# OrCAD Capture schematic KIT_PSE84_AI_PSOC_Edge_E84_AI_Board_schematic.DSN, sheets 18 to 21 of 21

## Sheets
18 21. Revision History
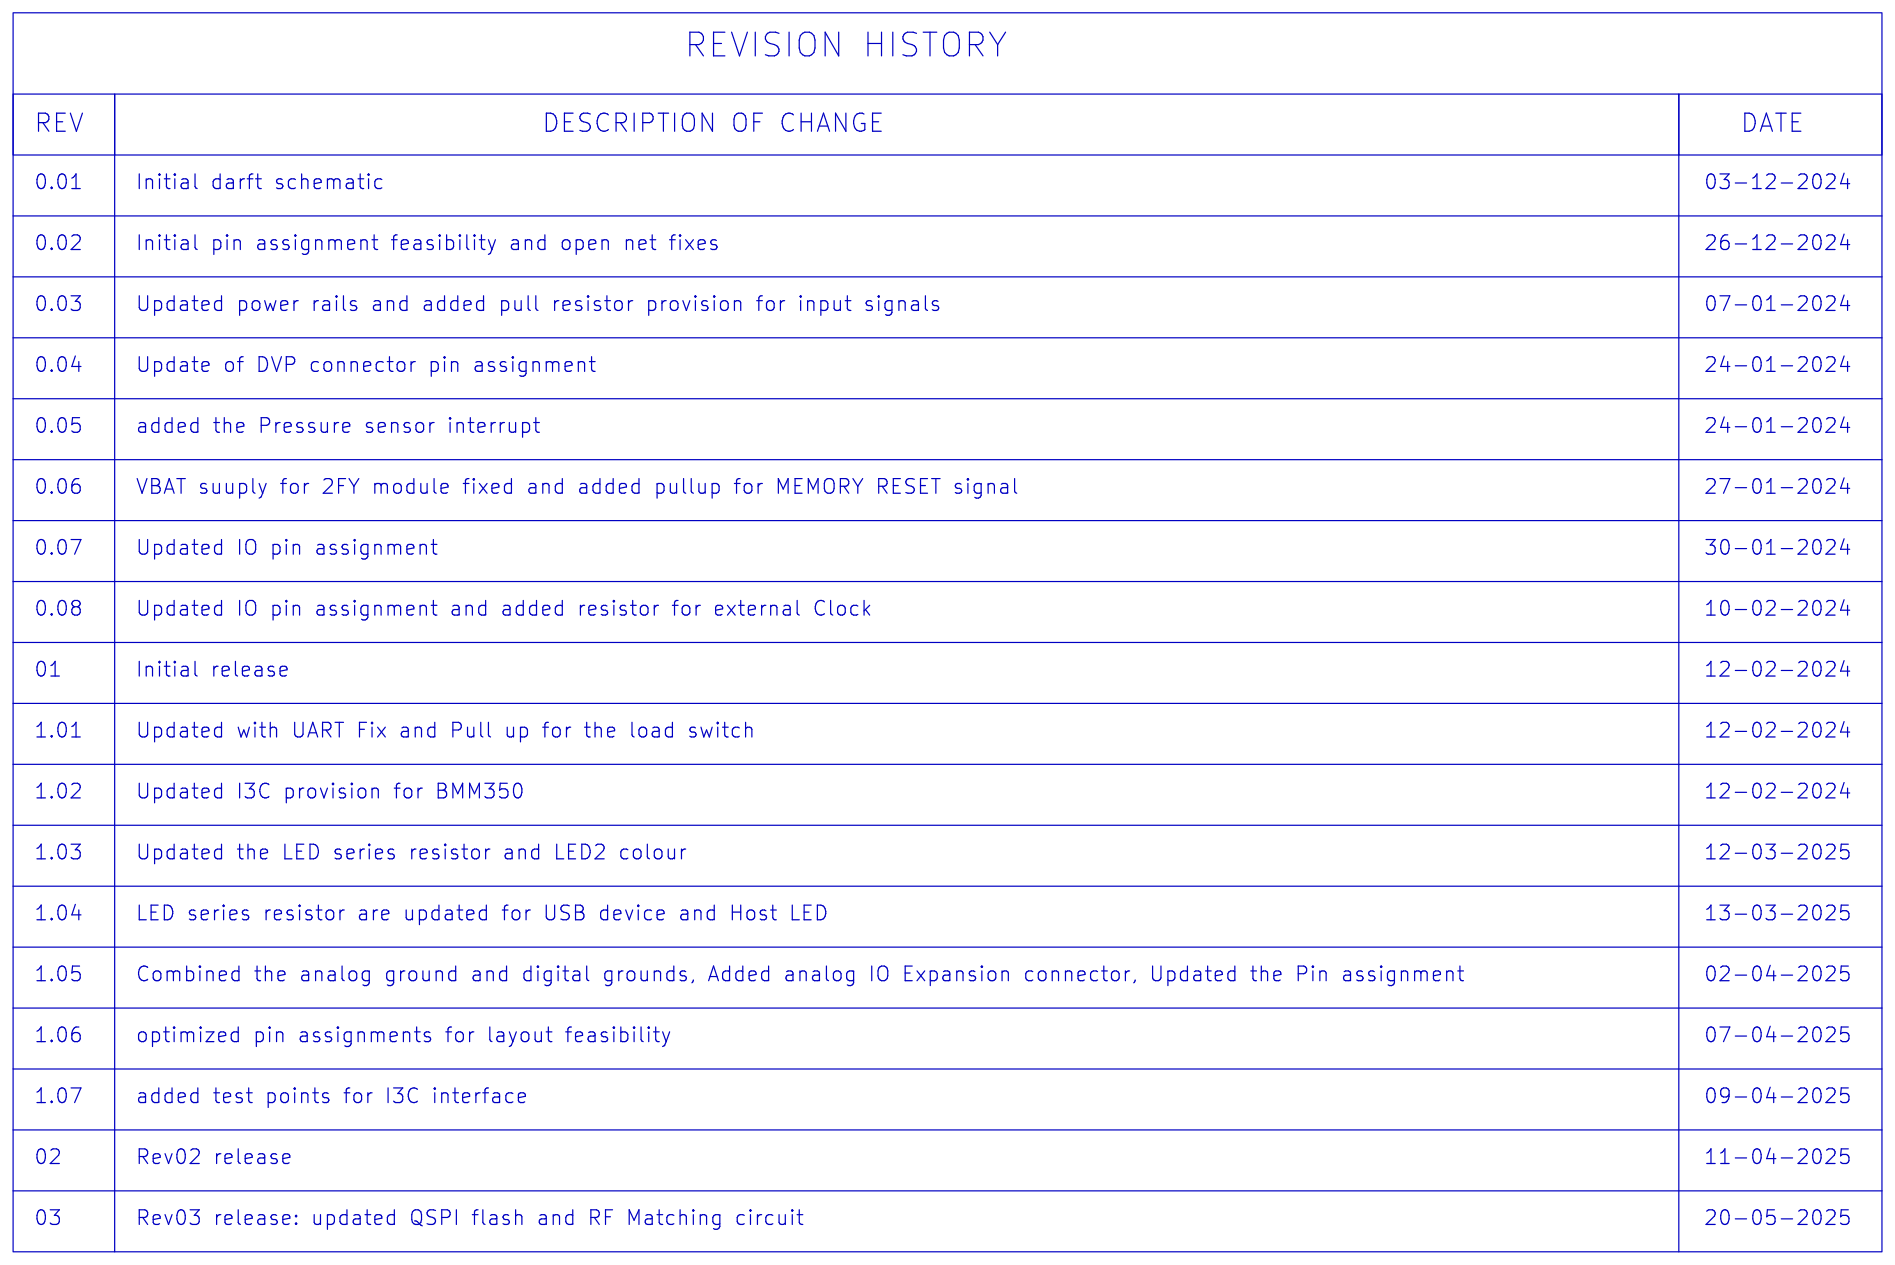
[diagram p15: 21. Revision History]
19 19. PSOC™ E84 Signals: size A4
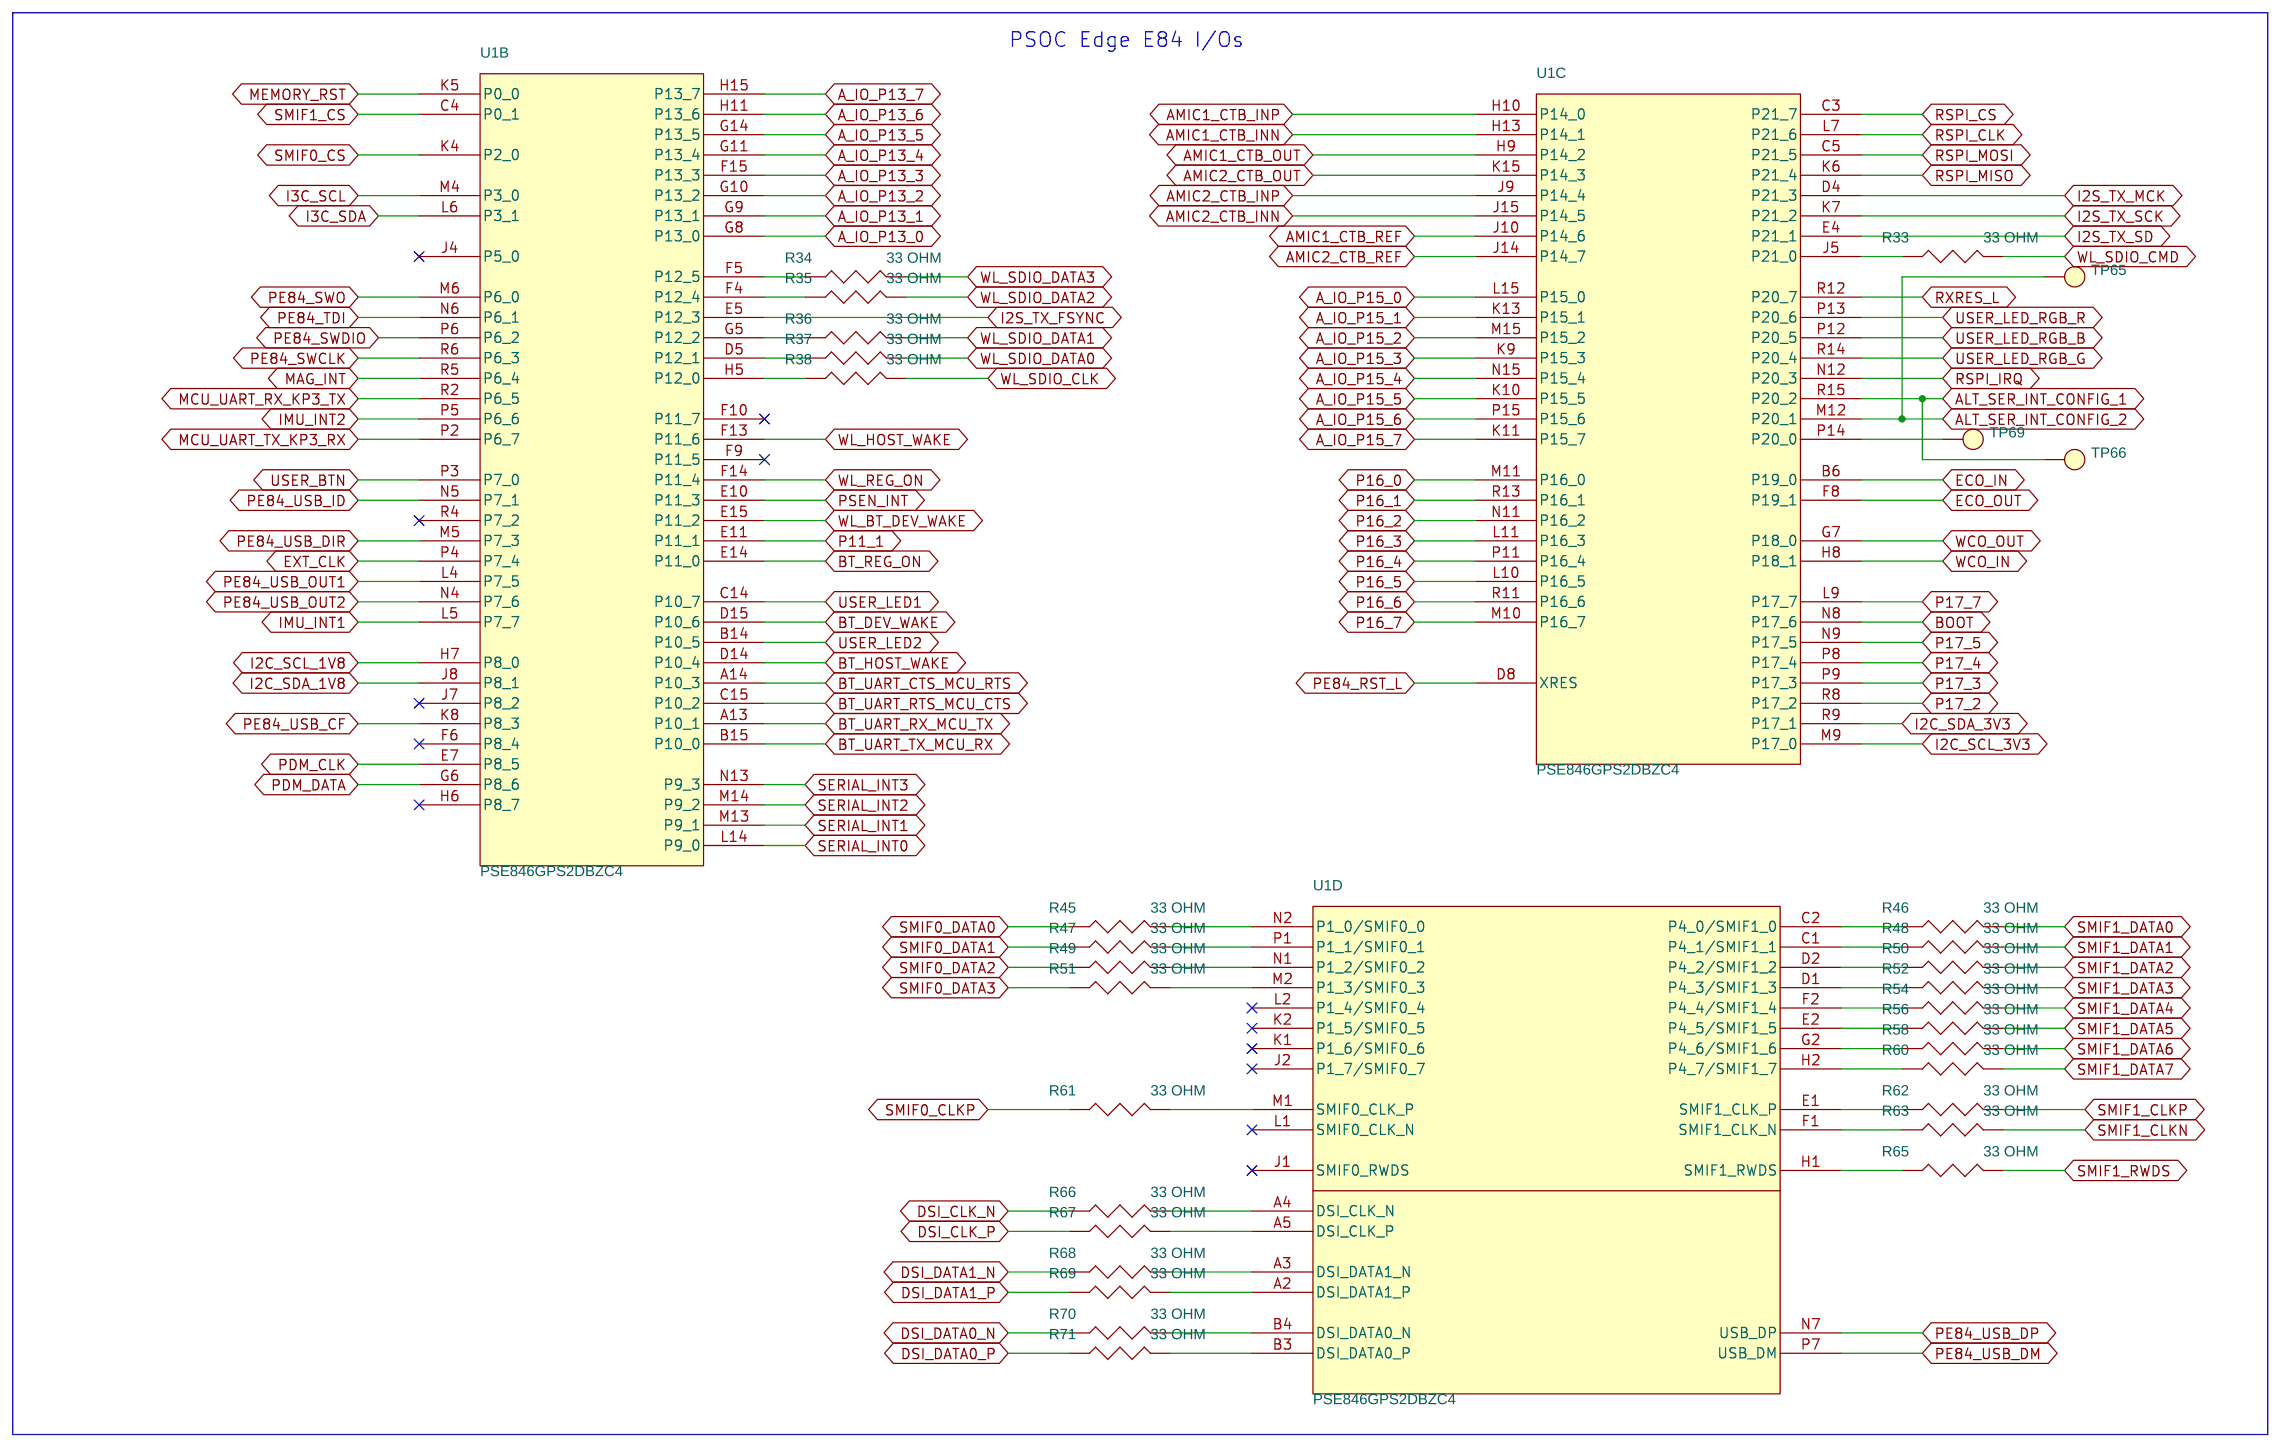
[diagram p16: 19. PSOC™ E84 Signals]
20 18. PSOC™ Edge E84 Power2: size A4
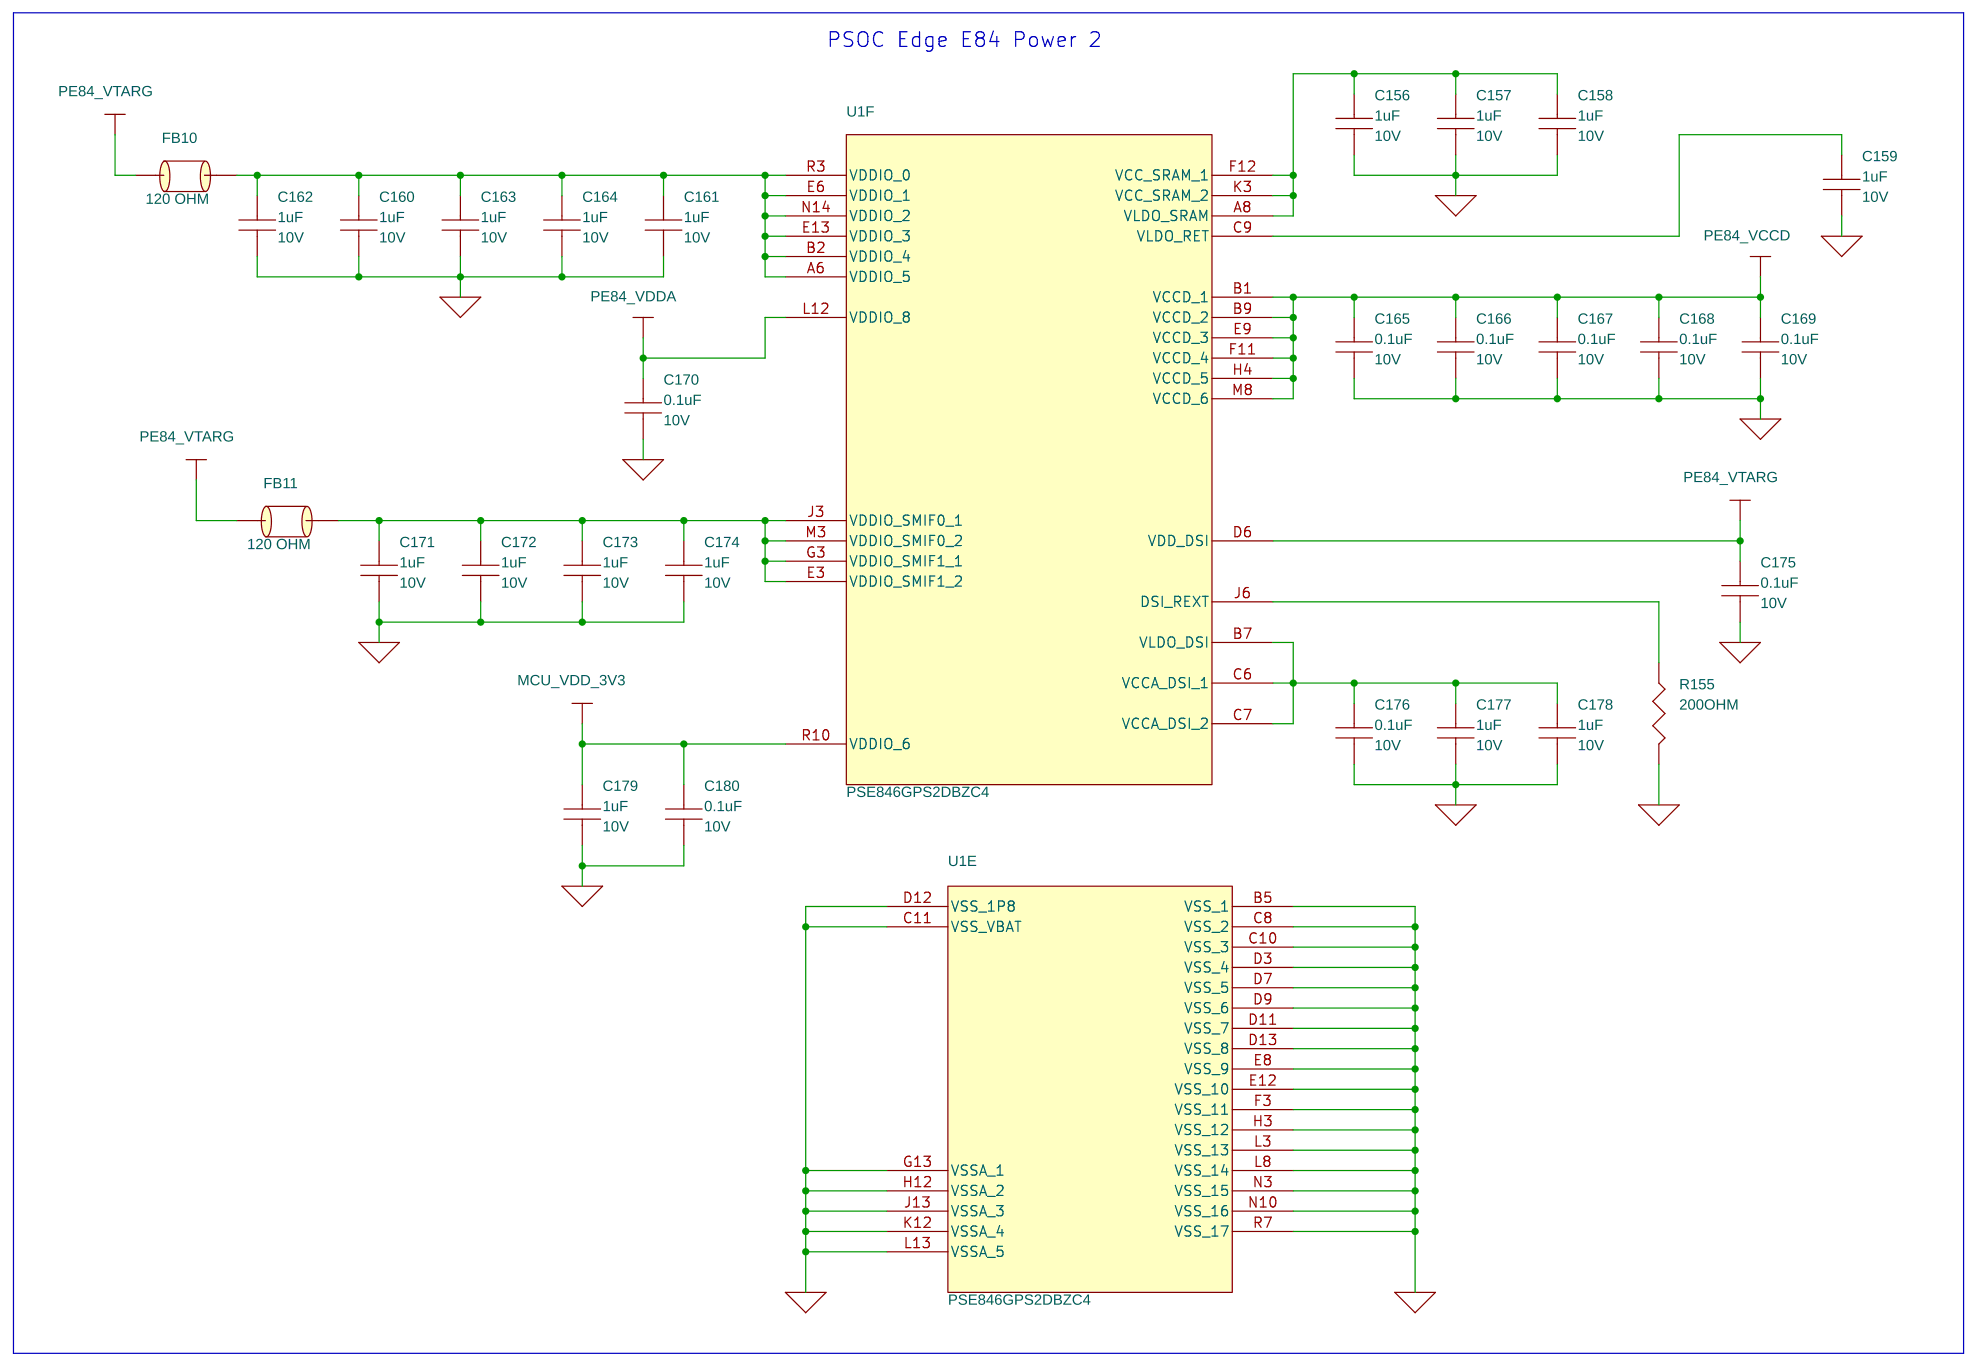
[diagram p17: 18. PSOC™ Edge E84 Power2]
21 17. PSOC™ Edge E84 Power1: size A4
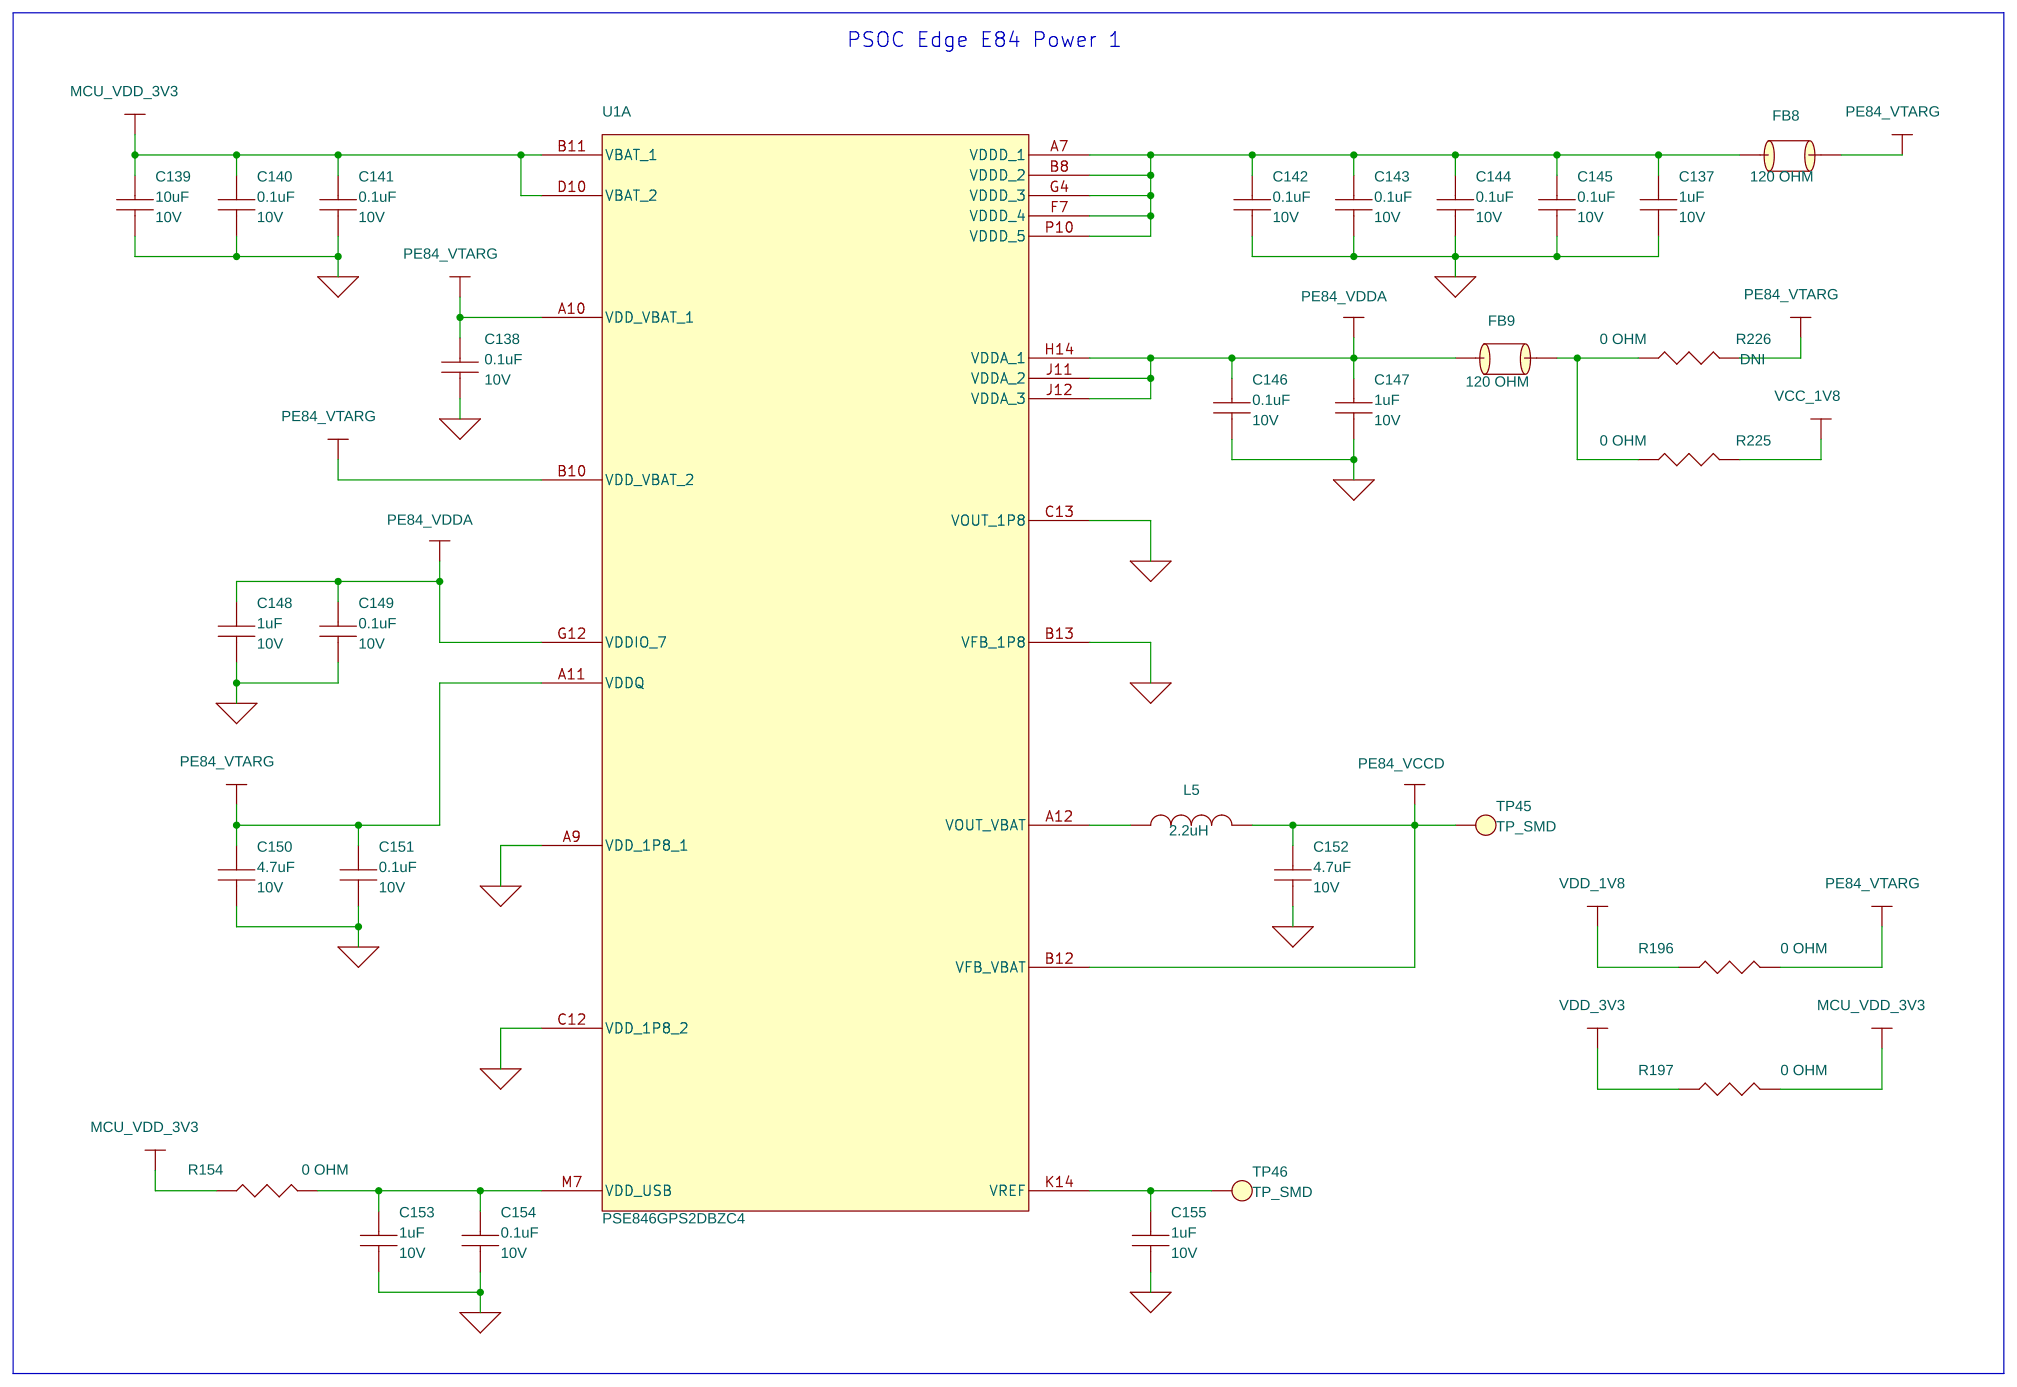
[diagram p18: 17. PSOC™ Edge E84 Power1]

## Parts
sheet 17. PSOC™ Edge E84 Power1
C137  1uF  [CAPC0603_0201N]
C138  0.1uF  [CAPC0603_0201N]
C139  10uF  [CAPC1005_0402N]
C140  0.1uF  [CAPC0603_0201N]
C141  0.1uF  [CAPC0603_0201N]
C142  0.1uF  [CAPC0603_0201N]
C143  0.1uF  [CAPC0603_0201N]
C144  0.1uF  [CAPC0603_0201N]
C145  0.1uF  [CAPC0603_0201N]
C146  0.1uF  [CAPC0603_0201N]
C147  1uF  [CAPC0603_0201N]
C148  1uF  [CAPC0603_0201N]
C149  0.1uF  [CAPC0603_0201N]
C150  4.7uF  [CAPC1005_0402N]
C151  0.1uF  [CAPC0603_0201N]
C152  4.7uF  [CAPC1005_0402N]
C153  1uF  [CAPC0603_0201N]
C154  0.1uF  [CAPC0603_0201N]
C155  1uF  [CAPC0603_0201N]
FB8  120 OHM  [INDC1005_0402M]
FB9  120 OHM  [INDC1005_0402M]
L5  2.2uH  [IND_74479276222C]
R154  0 OHM  [RESC1005_0402N]
R196  0 OHM  [RESC1005_0402N]
R197  0 OHM  [RESC1005_0402N]
R225  0 OHM  [RESC1005_0402N]
R226  0 OHM  [RESC1005_0402N]
TP45  TP_SMD  [ict_tp_smd_030rd_nsp]
TP46  TP_SMD  [ict_tp_smd_030rd_nsp]
sheet 18. PSOC™ Edge E84 Power2
C156  1uF  [CAPC0603_0201N]
C157  1uF  [CAPC0603_0201N]
C158  1uF  [CAPC0603_0201N]
C159  1uF  [CAPC0603_0201N]
C160  1uF  [CAPC0603_0201N]
C161  1uF  [CAPC0603_0201N]
C162  1uF  [CAPC0603_0201N]
C163  1uF  [CAPC0603_0201N]
C164  1uF  [CAPC0603_0201N]
C165  0.1uF  [CAPC0603_0201N]
C166  0.1uF  [CAPC0603_0201N]
C167  0.1uF  [CAPC0603_0201N]
C168  0.1uF  [CAPC0603_0201N]
C169  0.1uF  [CAPC0603_0201N]
C170  0.1uF  [CAPC0603_0201N]
C171  1uF  [CAPC0603_0201N]
C172  1uF  [CAPC0603_0201N]
C173  1uF  [CAPC0603_0201N]
C174  1uF  [CAPC0603_0201N]
C175  0.1uF  [CAPC0603_0201N]
C176  0.1uF  [CAPC0603_0201N]
C177  1uF  [CAPC0603_0201N]
C178  1uF  [CAPC0603_0201N]
C179  1uF  [CAPC0603_0201N]
C180  0.1uF  [CAPC0603_0201N]
FB10  120 OHM  [INDC1005_0402M]
FB11  120 OHM  [INDC1005_0402M]
R155  200OHM  [RESC0603_0201N]
U1  PSE846GPS2DBZC4  [BGA220C65P15X15_1000X1000X100_EXPLORER]  (sections A,B,C,D,E,F)
sheet 19. PSOC™ E84 Signals
R33  33 OHM  [RESC0603_0201N]
R34  33 OHM  [RESC0603_0201N]
R35  33 OHM  [RESC0603_0201N]
R36  33 OHM  [RESC0603_0201N]
R37  33 OHM  [RESC0603_0201N]
R38  33 OHM  [RESC0603_0201N]
R45  33 OHM  [RESC0603_0201N]
R46  33 OHM  [RESC0603_0201N]
R47  33 OHM  [RESC0603_0201N]
R48  33 OHM  [RESC0603_0201N]
R49  33 OHM  [RESC0603_0201N]
R50  33 OHM  [RESC0603_0201N]
R51  33 OHM  [RESC0603_0201N]
R52  33 OHM  [RESC0603_0201N]
R54  33 OHM  [RESC0603_0201N]
R56  33 OHM  [RESC0603_0201N]
R58  33 OHM  [RESC0603_0201N]
R60  33 OHM  [RESC0603_0201N]
R61  33 OHM  [RESC0603_0201N]
R62  33 OHM  [RESC0603_0201N]
R63  33 OHM  [RESC0603_0201N]
R65  33 OHM  [RESC0603_0201N]
R66  33 OHM  [RESC0603_0201N]
R67  33 OHM  [RESC0603_0201N]
R68  33 OHM  [RESC0603_0201N]
R69  33 OHM  [RESC0603_0201N]
R70  33 OHM  [RESC0603_0201N]
R71  33 OHM  [RESC0603_0201N]
TP65  TP_SMD  [ict_tp_smd_030rd_nsp]
TP66  TP_SMD  [ict_tp_smd_030rd_nsp]
TP69  TP_SMD  [ict_tp_smd_030rd_nsp]

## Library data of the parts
C137 C147 C148 C153 C155-C164 C171-C174 C177-C179 = CAP-NP: CAP, CER, 1uF, 20%, 10V, X5R, 0201; Approved: Approved; CY_PN: 510-61183-01; Device File: 510-60276-01; Device_File: 510-61183-01; Dielectric: X5R; FPLIST: CAPC0603_0201N,CAPC0603_0201Q; Lifecycle: Active; Manufacturer: Murata; Manufacturer_PN: GRM033R61A105ME15D; Operating_Temp: -55°C ~ 85°C; Package: 0201; Part Status: In Prod; Part_Status: In prod; Tolerance: 20%; Voltage: 10V
C138 C140-C146 C149 C151 C154 C165-C170 C175 C176 C180 = CAP-NP: CAP, CER, 0.1uF, 10%, X5R, 10V, 0201; Approved: Approved; CY_PN: 510-60777-01; Device_File: 510-60777-01; Dielectric: X5R; FPLIST: CAPC0603_0201N,CAPC0603_0201Q; Lifecycle: Active; Manufacturer: Wurth; Manufacturer_PN: 885012104002; Operating_Temp: -55°C ~ 85°C; Package: 0201; Part_Status: In Prod; Tolerance: 0.1; Voltage: 10V
C139 = CAP-NP: CAP, CER, 10uF, 20%, X5R, 10V, 0402; Approved: Approved; CY_PN: 510-60337-01; Device_File: 510-60337-01; Dielectric: X5R; FPLIST: CAPC1005_0402N,CAPC1005_0402M; Lifecycle: Active; Manufacturer: Wurth; Manufacturer_PN: 885012105022; Operating_Temp: -55°C ~ 85°C; Package: 0402; Part_Status: Unrel; Tolerance: 20%; Voltage: 10V
C150 C152 = CAP-NP: CAP, CER, 4.7uF, 20%, X5R, 10V, 0402; Approved: Approved; CY_PN: 510-60422-01; Device_File: 510-60422-01; Dielectric: X5R; FPLIST: CAPC1005_0402N,CAPC1005_0402M,capc1005_is0402q; Lifecycle: Active; Manufacturer: Murata; Manufacturer_PN: GRM155R61A475MEAAD; Operating_Temp: -55°C ~ 85°C; Package: 0402; Part_Status: In Prod; Tolerance: 20%; Voltage: 10V
FB8-FB11 = FB: IND, FERRITE BEAD, 120 OHM, 0402, 1LN; Approved: Approved; CY_PN: 520-60217-01; Current: 2A; DB_Status: Verified; Device_File: 520-60217-01; ESR: 55mOHM; FPLIST: INDC1005_0402M,INDC1005_0402N,INDC1005_0402L; Lifecycle: Active; Manufacturer: Murata; Manufacturer_PN: BLM15PX121SN1D; Material: Ferrite; Operating_Temp: -55°C ~ 125°C; Package: SMD; Part_Status: Unrel; Part_Type: Ferrite Bead; Tolerance: 25%
L5 = IND: IND, FIXED, SHIELDED, 2.2uH, 20%, 2.6A, 135MOHM, 0806, SMD; Approved: Approved; CY_PN: 520-60354-01; Current: 2.6A; DB_Status: Verified; Device_File: 520-60354-01; ESR: 135mOHM; Lifecycle: Active; Manufacturer: Würth Elektronik; Manufacturer_PN: 74479276222C; Material: shielded; Operating_Temp: -40°C ~ 125°C; Package: 0806; Part_Status: Unrel; Part_Type: Inductor; Tolerance: ±20%
R154 R225 = RES: RES, FIXED, 0 OHM, JUMPER, 1A, 1/16W, 0402; Approved: Approved; CY_PN: 500-60344-01; Device_File: 500-60344-01; FPLIST: RESC1005_0402N,RESC1005_0402M; Lifecycle: Active; Manufacturer: Wurth; Manufacturer_PN: 560112110001; Operating_Temp: -55°C ~ 155°C; Package: 0402; Part_Status: In Prod; Rating: 1/16W; Tolerance: JUMPER
R196 R197 = RES: RES, FIXED, 0 OHM, JUMPER, 1A, 1/16W, 0402; Approved: Approved; CY_PN: 500-60344-01; Device File: 500-60037-01; Device_File: 500-60344-01; FPLIST: RESC1005_0402N,RESC1005_0402M; Lifecycle: Active; Manufacturer: Wurth; Manufacturer_PN: 560112110001; Operating_Temp: -55°C ~ 155°C; Package: 0402; Part_Status: In Prod; Rating: 1/16W; Tolerance: JUMPER
R226 = RES: RES, FIXED, 0 OHM, JUMPER, 1A, 1/16W, 0402; Approved: Approved; CY_PN: 500-60344-01; DNI: DNI; Device_File: 500-60344-01; FPLIST: RESC1005_0402N,RESC1005_0402M; Lifecycle: Active; Manufacturer: Wurth; Manufacturer_PN: 560112110001; Operating_Temp: -55°C ~ 155°C; Package: 0402; Part_Status: In Prod; Rating: 1/16W; Tolerance: JUMPER
TP45 TP46 TP65 TP66 TP69 = TP_SMD: TestPoint, PCB, Circle, 0.75mm, SMD; Approved: Approved; CY_PN: NA; DNI: DNI; Device_File: NA; Lifecycle: NA; Manufacturer: NA; Manufacturer_PN: NA; Part_Status: NA
R155 = RES: RES 200 OHM 1% 1/20W 0201; Approved: Approved; CY_PN: 500-61242-01; Device_File: 500-61242-01; FPLIST: RESC0603_0201N,RESC0603_0201Q; Manufacturer: Stackpole; Manufacturer_PN: RMCF0201FT200R; Package: 0201; Rating: 1/20W
U1 = Explorer_220BGA_rev9280_May22: IC, Infineon, MCU, PSoC E84, Dual Core, 50/400MHz, 1.8 V / 2.7 to 4.8 V, BGA-220; Approved: Approved; Description1: 6.5MB SRAM/0.5MB RRAM, PSA L2 Security, 400MHz M55, 200MHz M33; FPLIST: BGA220C65P15X15_1000X1000X100_EXPLORER,SKT_CSFPBGA220-0P65-KG1030-PFA02-INF1_A1_CONTECH,SKT_220BHM65A01G_PLASTRONICS; Lifecycle: Design Intent; Manufacturer: Infineon; Operating_Temp: 0 °C to +70 °C; Operating_Voltage: 1.8 V / 2.7 - 4.8 V; Package: 220-FBGA; Part_Status: Unrel
R33-R37 R45-R52 R54 R56 R58 R60-R63 R65 = RES: RES, Fixed, 33 OHM, 5%, 1/20W, 0201; Approved: Approved; CY_PN: 500-60980-01; Device_File: 500-60980-01; FPLIST: RESC0603_0201N,RESC0603_0201Q; Lifecycle: Active; Manufacturer: Yageo; Manufacturer_PN: RC0201JR-0733RP; Operating_Temp: -55°C ~ 125°C; Package: 0201; Part_Status: In Prod; Rating: 1/20W; SIGNAL_MODEL: RES_RESC0603_0201N_DISCRETE_33_OHM_33_OHM; Tolerance: 5%
R38 R66-R71 = RES: RES, Fixed, 33 OHM, 5%, 1/20W, 0201; Approved: Approved; CY_PN: 500-60980-01; Device_File: 500-60980-01; FPLIST: RESC0603_0201N,RESC0603_0201Q; Lifecycle: Active; Manufacturer: Yageo; Manufacturer_PN: RC0201JR-0733RP; Operating_Temp: -55°C ~ 125°C; Package: 0201; Part_Status: In Prod; Rating: 1/20W; Tolerance: 5%

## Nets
GND_SIGNAL: C137.2 C138.2 C139.2 C140.2 C141.2 C142.2 C143.2 C144.2 C145.2 C146.2 C147.2 C148.2 C149.2 C150.2 C151.2 C152.2 C153.2 C154.2 C155.2 C156.2 C157.2 C158.2 C159.2 C160.2 C161.2 C162.2 C163.2 C164.2 C165.2 C166.2 C167.2 C168.2 C169.2 C170.2 C171.2 C172.2 C173.2 C174.2 C175.2 C176.2 C177.2 C178.2 C179.2 C180.2 R155.2 U1.A9(VDD_1P8_1) U1.B5(VSS_1) U1.B13(VFB_1P8) U1.C8(VSS_2) U1.C10(VSS_3) U1.C11(VSS_VBAT) U1.C12(VDD_1P8_2) U1.C13(VOUT_1P8) U1.D3(VSS_4) U1.D7(VSS_5) U1.D9(VSS_6) U1.D11(VSS_7) U1.D12(VSS_1P8) U1.D13(VSS_8) U1.E8(VSS_9) U1.E12(VSS_10) U1.F3(VSS_11) U1.G13(VSSA_1) U1.H3(VSS_12) U1.H12(VSSA_2) U1.J13(VSSA_3) U1.K12(VSSA_4) U1.L3(VSS_13) U1.L8(VSS_14) U1.L13(VSSA_5) U1.N3(VSS_15) U1.N10(VSS_16) U1.R7(VSS_17) ; also on sheet 5 6 7 8 9 10 11 12 13 14 15 16 17
VCC_1V8: R225.1 ; also on sheet 7 11 13 16
VDD_1V8: R196.2 ; also on sheet 5 6 7 9 10 12 13 14 15 16
VDD_3V3: R197.2 ; also on sheet 6 7 9 12 13 15 17
A_IO_P13_0: U1.G8(P13_0) ; also on sheet 13
A_IO_P13_1: U1.G9(P13_1) ; also on sheet 13
A_IO_P13_2: U1.G10(P13_2) ; also on sheet 13
A_IO_P13_3: U1.F15(P13_3) ; also on sheet 13
A_IO_P13_4: U1.G11(P13_4) ; also on sheet 13
A_IO_P13_5: U1.G14(P13_5) ; also on sheet 13
A_IO_P13_6: U1.H11(P13_6) ; also on sheet 13
A_IO_P13_7: U1.H15(P13_7) ; also on sheet 13
A_IO_P15_0: U1.L15(P15_0) ; also on sheet 13
A_IO_P15_1: U1.K13(P15_1) ; also on sheet 13
A_IO_P15_2: U1.M15(P15_2) ; also on sheet 13
A_IO_P15_3: U1.K9(P15_3) ; also on sheet 13
A_IO_P15_4: U1.N15(P15_4) ; also on sheet 13
A_IO_P15_5: U1.K10(P15_5) ; also on sheet 13
A_IO_P15_6: U1.P15(P15_6) ; also on sheet 13
A_IO_P15_7: U1.K11(P15_7) ; also on sheet 13
ALT_SER_INT_CONFIG_1: TP66.1(TP) U1.R15(P20_2) ; also on sheet 13
ALT_SER_INT_CONFIG_2: TP65.1(TP) U1.M12(P20_1) ; also on sheet 13
AMIC1_CTB_INN: U1.H13(P14_1) ; also on sheet 16
AMIC1_CTB_INP: U1.H10(P14_0) ; also on sheet 16
AMIC1_CTB_OUT: U1.H9(P14_2) ; also on sheet 16
AMIC1_CTB_REF: U1.J10(P14_6) ; also on sheet 16
AMIC2_CTB_INN: U1.J15(P14_5) ; also on sheet 16
AMIC2_CTB_INP: U1.J9(P14_4) ; also on sheet 16
AMIC2_CTB_OUT: U1.K15(P14_3) ; also on sheet 16
AMIC2_CTB_REF: U1.J14(P14_7) ; also on sheet 16
BOOT: U1.N8(P17_6) ; also on sheet 9
BT_DEV_WAKE: U1.D15(P10_6) ; also on sheet 12
BT_HOST_WAKE: U1.D14(P10_4) ; also on sheet 12
BT_REG_ON: U1.E14(P11_0) ; also on sheet 12
BT_UART_CTS_MCU_RTS: U1.A14(P10_3) ; also on sheet 12
BT_UART_RTS_MCU_CTS: U1.C15(P10_2) ; also on sheet 12
BT_UART_RX_MCU_TX: U1.A13(P10_1) ; also on sheet 12
BT_UART_TX_MCU_RX: U1.B15(P10_0) ; also on sheet 12
DSI_CLK_N: R66.1 ; also on sheet 17
DSI_CLK_P: R67.1 ; also on sheet 17
DSI_DATA0_N: R70.1 ; also on sheet 17
DSI_DATA0_P: R71.1 ; also on sheet 17
DSI_DATA1_N: R68.1 ; also on sheet 17
DSI_DATA1_P: R69.1 ; also on sheet 17
ECO_IN: U1.B6(P19_0) ; also on sheet 9
ECO_OUT: U1.F8(P19_1) ; also on sheet 9
EXT_CLK: U1.P4(P7_4) ; also on sheet 9
I2C_SCL_1V8: U1.H7(P8_0) ; also on sheet 8 10 15
I2C_SCL_3V3: U1.M9(P17_0) ; also on sheet 13 17
I2C_SDA_1V8: U1.J8(P8_1) ; also on sheet 8 10 15
I2C_SDA_3V3: U1.R9(P17_1) ; also on sheet 13 17
I2S_TX_FSYNC: U1.E5(P12_3) ; also on sheet 15
I2S_TX_MCK: U1.D4(P21_3) ; also on sheet 15
I2S_TX_SCK: U1.K7(P21_2) ; also on sheet 15
I2S_TX_SD: U1.E4(P21_1) ; also on sheet 15
I3C_SCL: U1.M4(P3_0) ; also on sheet 10 13
I3C_SDA: U1.L6(P3_1) ; also on sheet 10 13
IMU_INT1: U1.L5(P7_7) ; also on sheet 10
IMU_INT2: U1.P5(P6_6) ; also on sheet 10
MAG_INT: U1.R5(P6_4) ; also on sheet 10
MCU_UART_RX_KP3_TX: U1.R2(P6_5) ; also on sheet 8
MCU_UART_TX_KP3_RX: U1.P2(P6_7) ; also on sheet 8
MCU_VDD_3V3: C139.1 C140.1 C141.1 C179.1 C180.1 R154.2 R197.1 U1.B11(VBAT_1) U1.D10(VBAT_2) U1.R10(VDDIO_6)
MEMORY_RST: U1.K5(P0_0) ; also on sheet 14
P11_1: U1.E11(P11_1) ; also on sheet 13
P16_0: U1.M11(P16_0) ; also on sheet 13
P16_1: U1.R13(P16_1) ; also on sheet 13
P16_2: U1.N11(P16_2) ; also on sheet 13
P16_3: U1.L11(P16_3) ; also on sheet 13
P16_4: U1.P11(P16_4) ; also on sheet 13
P16_5: U1.L10(P16_5) ; also on sheet 13
P16_6: U1.R11(P16_6) ; also on sheet 13
P16_7: U1.M10(P16_7) ; also on sheet 13
P17_2: U1.R8(P17_2) ; also on sheet 13
P17_3: U1.P9(P17_3) ; also on sheet 13
P17_4: U1.P8(P17_4) ; also on sheet 13
P17_5: U1.N9(P17_5) ; also on sheet 13
P17_7: U1.L9(P17_7) ; also on sheet 13
PDM_CLK: U1.E7(P8_5) ; also on sheet 10
PDM_DATA: U1.G6(P8_6) ; also on sheet 10
PE84_RST_L: U1.D8(XRES) ; also on sheet 8 9
PE84_SWCLK: U1.R6(P6_3) ; also on sheet 8 9
PE84_SWDIO: U1.P6(P6_2) ; also on sheet 8 9
PE84_SWO: U1.M6(P6_0) ; also on sheet 9
PE84_TDI: U1.N6(P6_1) ; also on sheet 9
PE84_USB_CF: U1.K8(P8_3) ; also on sheet 6
PE84_USB_DIR: U1.M5(P7_3) ; also on sheet 6
PE84_USB_DM: U1.P7(USB_DM) ; also on sheet 6
PE84_USB_DP: U1.N7(USB_DP) ; also on sheet 6
PE84_USB_ID: U1.N5(P7_1) ; also on sheet 5 6
PE84_USB_OUT1: U1.L4(P7_5) ; also on sheet 6
PE84_USB_OUT2: U1.N4(P7_6) ; also on sheet 6
PE84_VCCD: C152.1 C165.1 C166.1 C167.1 C168.1 C169.1 L5.2 TP45.1(TP) U1.B1(VCCD_1) U1.B9(VCCD_2) U1.B12(VFB_VBAT) U1.E9(VCCD_3) U1.F11(VCCD_4) U1.H4(VCCD_5) U1.M8(VCCD_6)
PE84_VDDA: C146.1 C147.1 C148.1 C149.1 C170.1 FB9.2 U1.G12(VDDIO_7) U1.H14(VDDA_1) U1.J11(VDDA_2) U1.J12(VDDA_3) U1.L12(VDDIO_8)
PE84_VTARG: C138.1 C150.1 C151.1 C175.1 FB8.1 FB10.2 FB11.2 R196.1 R226.1 U1.A10(VDD_VBAT_1) U1.A11(VDDQ) U1.B10(VDD_VBAT_2) U1.D6(VDD_DSI) ; also on sheet 8 9
PSEN_INT: U1.E10(P11_3) ; also on sheet 10
RSPI_CLK: U1.L7(P21_6) ; also on sheet 11
RSPI_CS: U1.C3(P21_7) ; also on sheet 11
RSPI_IRQ: U1.N12(P20_3) ; also on sheet 11
RSPI_MISO: U1.K6(P21_4) ; also on sheet 11
RSPI_MOSI: U1.C5(P21_5) ; also on sheet 11
RXRES_L: U1.R12(P20_7) ; also on sheet 11
SERIAL_INT0: U1.L14(P9_0) ; also on sheet 13
SERIAL_INT1: U1.M13(P9_1) ; also on sheet 13
SERIAL_INT2: U1.M14(P9_2) ; also on sheet 13
SERIAL_INT3: U1.N13(P9_3) ; also on sheet 13
SMIF0_CLKP: R61.1 ; also on sheet 14
SMIF0_CS: U1.K4(P2_0) ; also on sheet 14
SMIF0_DATA0: R45.1 ; also on sheet 14
SMIF0_DATA1: R47.1 ; also on sheet 14
SMIF0_DATA2: R49.1 ; also on sheet 14
SMIF0_DATA3: R51.1 ; also on sheet 14
SMIF1_CLKN: R63.2 ; also on sheet 14
SMIF1_CLKP: R62.2 ; also on sheet 14
SMIF1_CS: U1.C4(P0_1) ; also on sheet 14
SMIF1_DATA0: R46.2 ; also on sheet 14
SMIF1_DATA1: R48.2 ; also on sheet 14
SMIF1_DATA2: R50.2 ; also on sheet 14
SMIF1_DATA3: R52.2 ; also on sheet 14
SMIF1_DATA4: R54.2 ; also on sheet 14
SMIF1_DATA5: R56.2 ; also on sheet 14
SMIF1_DATA6: R58.2 ; also on sheet 14
SMIF1_DATA7: R60.2 ; also on sheet 14
SMIF1_RWDS: R65.2 ; also on sheet 14
USER_BTN: U1.P3(P7_0) ; also on sheet 9
USER_LED1: U1.C14(P10_7) ; also on sheet 9
USER_LED2: U1.B14(P10_5) ; also on sheet 9
USER_LED_RGB_B: U1.P12(P20_5) ; also on sheet 9
USER_LED_RGB_G: U1.R14(P20_4) ; also on sheet 9
USER_LED_RGB_R: U1.P13(P20_6) ; also on sheet 9
WCO_IN: U1.H8(P18_1) ; also on sheet 9
WCO_OUT: U1.G7(P18_0) ; also on sheet 9
WL_BT_DEV_WAKE: U1.E15(P11_2) ; also on sheet 12
WL_HOST_WAKE: U1.F13(P11_6) ; also on sheet 12
WL_REG_ON: U1.F14(P11_4) ; also on sheet 12
WL_SDIO_CLK: R38.2 ; also on sheet 12
WL_SDIO_CMD: R33.2 ; also on sheet 12
WL_SDIO_DATA0: R37.2 ; also on sheet 12
WL_SDIO_DATA1: R36.2 ; also on sheet 12
WL_SDIO_DATA2: R35.2 ; also on sheet 12
WL_SDIO_DATA3: R34.2 ; also on sheet 12
N17699019: C137.1 C142.1 C143.1 C144.1 C145.1 FB8.2 U1.A7(VDDD_1) U1.B8(VDDD_2) U1.F7(VDDD_4) U1.G4(VDDD_3) U1.P10(VDDD_5)
N17699233: FB9.1 R225.2 R226.2
N17699382: L5.1 U1.A12(VOUT_VBAT)
N17699478: C153.1 C154.1 R154.1 U1.M7(VDD_USB)
N17699488: C155.1 TP46.1(TP) U1.K14(VREF)
N17701248: C156.1 C157.1 C158.1 U1.A8(VLDO_SRAM) U1.F12(VCC_SRAM_1) U1.K3(VCC_SRAM_2)
N17701334: C159.1 U1.C9(VLDO_RET)
N17701356: C160.1 C161.1 C162.1 C163.1 C164.1 FB10.1 U1.A6(VDDIO_5) U1.B2(VDDIO_4) U1.E6(VDDIO_1) U1.E13(VDDIO_3) U1.N14(VDDIO_2) U1.R3(VDDIO_0)
N17701674: C171.1 C172.1 C173.1 C174.1 FB11.1 U1.E3(VDDIO_SMIF1_2) U1.G3(VDDIO_SMIF1_1) U1.J3(VDDIO_SMIF0_1) U1.M3(VDDIO_SMIF0_2)
N17701770: R155.1 U1.J6(DSI_REXT)
N17701786: C176.1 C177.1 C178.1 U1.B7(VLDO_DSI) U1.C6(VCCA_DSI_1) U1.C7(VCCA_DSI_2)
N17708163: R33.1 U1.J5(P21_0)
N17708171: R34.1 U1.F5(P12_5)
N17708201: R35.1 U1.F4(P12_4)
N17708259: R36.1 U1.G5(P12_2)
N17708293: R37.1 U1.D5(P12_1)
N17708327: R38.1 U1.H5(P12_0)
N17708399: TP69.1(TP) U1.P14(P20_0)
N17708861: R45.2 U1.N2(P1_0/SMIF0_0)
N17708863: R46.1 U1.C2(P4_0/SMIF1_0)
N17708893: R47.2 U1.P1(P1_1/SMIF0_1)
N17708895: R48.1 U1.C1(P4_1/SMIF1_1)
N17708925: R49.2 U1.N1(P1_2/SMIF0_2)
N17708927: R50.1 U1.D2(P4_2/SMIF1_2)
N17708957: R51.2 U1.M2(P1_3/SMIF0_3)
N17708959: R52.1 U1.D1(P4_3/SMIF1_3)
N17708991: R54.1 U1.F2(P4_4/SMIF1_4)
N17709023: R56.1 U1.E2(P4_5/SMIF1_5)
N17709055: R58.1 U1.G2(P4_6/SMIF1_6)
N17709075: R60.1 U1.H2(P4_7/SMIF1_7)
N17709105: R61.2 U1.M1(SMIF0_CLK_P)
N17709107: R62.1 U1.E1(SMIF1_CLK_P)
N17709123: R63.1 U1.F1(SMIF1_CLK_N)
N17709155: R65.1 U1.H1(SMIF1_RWDS)
N17709188: R66.2 U1.A4(DSI_CLK_N)
N17709192: R67.2 U1.A5(DSI_CLK_P)
N17709220: R68.2 U1.A3(DSI_DATA1_N)
N17709224: R69.2 U1.A2(DSI_DATA1_P)
N17709256: R70.2 U1.B4(DSI_DATA0_N)
N17709266: R71.2 U1.B3(DSI_DATA0_P)

Not connected (* = marked no-connect by the designer): U1 F6(P8_4)* F9(P11_5)* F10(P11_7)* H6(P8_7)* J1(SMIF0_RWDS)* J2(P1_7/SMIF0_7)* J4(P5_0)* J7(P8_2)* K1(P1_6/SMIF0_6)* K2(P1_5/SMIF0_5)* L1(SMIF0_CLK_N)* L2(P1_4/SMIF0_4)* R4(P7_2)*

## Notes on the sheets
sheet 18
- REVISION HISTORY
- REV
- DESCRIPTION OF CHANGE
- DATE
- 0.01
- Initial darft schematic
- 03-12-2024
- 0.02
- Initial pin assignment feasibility and open net fixes
- 26-12-2024
- 0.03
- Updated power rails and added pull resistor provision for input signals
- 07-01-2024
- 0.04
- Update of DVP connector pin assignment
- 24-01-2024
- 0.05
- added the Pressure sensor interrupt
- 24-01-2024
- 0.06
- VBAT suuply for 2FY module fixed and added pullup for MEMORY RESET signal
- 27-01-2024
- 0.07
- Updated IO pin assignment
- 30-01-2024
- 0.08
- Updated IO pin assignment and added resistor for external Clock
- 10-02-2024
- 01
- Initial release
- 12-02-2024
- 1.01
- Updated with UART Fix and Pull up for the load switch
- 12-02-2024
- 1.02
- Updated I3C provision for BMM350
- 12-02-2024
- 1.03
- Updated the LED series resistor and LED2 colour
- 12-03-2025
- 1.04
- LED series resistor are updated for USB device and Host LED
- 13-03-2025
- 1.05
- Combined the analog ground and digital grounds, Added analog IO Expansion connector, Updated the Pin assignment
- 02-04-2025
- 1.06
- optimized pin assignments for layout feasibility
- 07-04-2025
- 1.07
- added test points for I3C interface
- 09-04-2025
- 02
- Rev02 release
- 11-04-2025
- 03
- Rev03 release: updated QSPI flash and RF Matching circuit
- 20-05-2025
sheet 19
- PSOC Edge E84 I/Os
sheet 20
- PSOC Edge E84 Power 2
sheet 21
- PSOC Edge E84 Power 1
